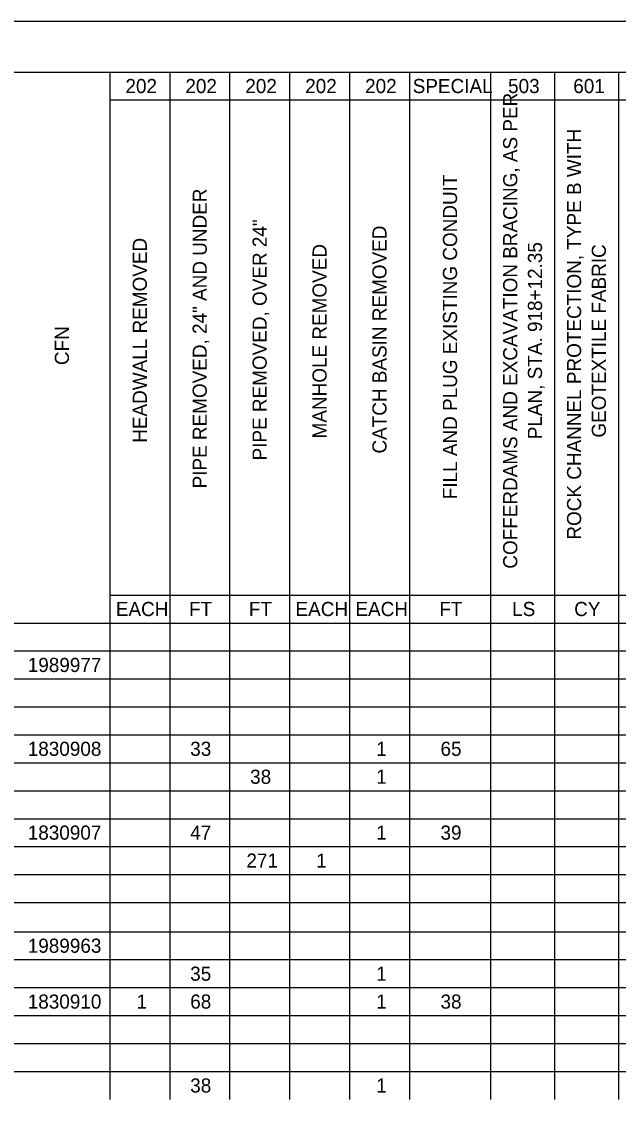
# Model space of a CAD drawing. Extents: x 0.2 to 34.2, y 0 to 22.
# Drawn here: x 9 to 14.91, y 11.35 to 22.03 of the extents above; entities that cross this region are included whole.
import ezdxf

# ---------------------------------------------------------------- set-up
doc = ezdxf.new("R2010")
doc.units = 0
for name, color, linetype in [('SH_Border', 7, 'Continuous'), ('SH_Cut_Line', 7, 'Continuous'), ('SH_Text', 7, 'Continuous')]:
    doc.layers.add(name, color=color, linetype=linetype)

msp = doc.modelspace()

# ---------------------------------------------------------------- linework, layer by layer
at = {"layer": 'SH_Border'}
msp.add_lwpolyline([(1.692, 21.525), (33.692, 21.525), (33.692, 0.525), (1.692, 0.525)], close=True, dxfattribs=at)
at = {"layer": 'SH_Cut_Line'}
msp.add_lwpolyline([(0.192, 0.025), (34.192, 0.025), (34.192, 22.025), (0.192, 22.025)], close=True, dxfattribs=at)
at = {"layer": 'SH_Text'}
for p, q in [((8.254, 21.525), (13.643, 21.525)), ((9.875, 21.525), (9.875, 21.249)), ((10.468, 21.525), (10.468, 21.249)), ((11.06, 21.525), (11.06, 21.249)), ((11.653, 21.525), (11.653, 21.249)), ((12.246, 21.525), (12.246, 21.249)), ((12.839, 21.525), (12.839, 21.249)), ((13.643, 21.525), (14.276, 21.525)), ((13.643, 21.525), (13.643, 21.249)), ((14.276, 21.525), (14.908, 21.525)), ((14.276, 21.525), (14.276, 21.249)), ((14.908, 21.525), (15.54, 21.525)), ((14.908, 21.525), (14.908, 21.249)), ((9.875, 21.249), (13.643, 21.249)), ((9.875, 21.249), (9.875, 20.972)), ((10.468, 21.249), (10.468, 20.972)), ((11.06, 21.249), (11.06, 20.972)), ((11.653, 21.249), (11.653, 20.972)), ((12.246, 21.249), (12.246, 20.972)), ((12.839, 21.249), (12.839, 20.972)), ((13.643, 21.249), (14.276, 21.249)), ((13.643, 21.249), (13.643, 20.972)), ((14.276, 21.249), (14.908, 21.249)), ((14.276, 21.249), (14.276, 20.972)), ((14.908, 21.249), (15.54, 21.249)), ((14.908, 21.249), (14.908, 20.972)), ((9.875, 20.972), (9.875, 20.695)), ((10.468, 20.972), (10.468, 20.695)), ((11.06, 20.972), (11.06, 20.695)), ((11.653, 20.972), (11.653, 20.695)), ((12.246, 20.972), (12.246, 20.695)), ((12.839, 20.972), (12.839, 20.695)), ((13.643, 20.972), (13.643, 20.695)), ((14.276, 20.972), (14.276, 20.695)), ((14.908, 20.972), (14.908, 20.695)), ((9.875, 20.695), (9.875, 20.418)), ((10.468, 20.695), (10.468, 20.418)), ((11.06, 20.695), (11.06, 20.418)), ((11.653, 20.695), (11.653, 20.418)), ((12.246, 20.695), (12.246, 20.418)), ((12.839, 20.695), (12.839, 20.418)), ((13.643, 20.695), (13.643, 20.418)), ((14.276, 20.695), (14.276, 20.418)), ((14.908, 20.695), (14.908, 20.418)), ((9.875, 20.418), (9.875, 20.142)), ((10.468, 20.418), (10.468, 20.142)), ((11.06, 20.418), (11.06, 20.142)), ((11.653, 20.418), (11.653, 20.142)), ((12.246, 20.418), (12.246, 20.142)), ((12.839, 20.418), (12.839, 20.142)), ((13.643, 20.418), (13.643, 20.142)), ((14.276, 20.418), (14.276, 20.142)), ((14.908, 20.418), (14.908, 20.142)), ((9.875, 20.142), (9.875, 19.865)), ((10.468, 20.142), (10.468, 19.865)), ((11.06, 20.142), (11.06, 19.865)), ((11.653, 20.142), (11.653, 19.865)), ((12.246, 20.142), (12.246, 19.865)), ((12.839, 20.142), (12.839, 19.865)), ((13.643, 20.142), (13.643, 19.865)), ((14.276, 20.142), (14.276, 19.865)), ((14.908, 20.142), (14.908, 19.865)), ((9.875, 19.865), (9.875, 19.588)), ((10.468, 19.865), (10.468, 19.588)), ((11.06, 19.865), (11.06, 19.588)), ((11.653, 19.865), (11.653, 19.588)), ((12.246, 19.865), (12.246, 19.588)), ((12.839, 19.865), (12.839, 19.588)), ((13.643, 19.865), (13.643, 19.588)), ((14.276, 19.865), (14.276, 19.588)), ((14.908, 19.865), (14.908, 19.588)), ((9.875, 19.588), (9.875, 19.312)), ((10.468, 19.588), (10.468, 19.312)), ((11.06, 19.588), (11.06, 19.312)), ((11.653, 19.588), (11.653, 19.312)), ((12.246, 19.588), (12.246, 19.312)), ((12.839, 19.588), (12.839, 19.312)), ((13.643, 19.588), (13.643, 19.312)), ((14.276, 19.588), (14.276, 19.312)), ((14.908, 19.588), (14.908, 19.312)), ((9.875, 19.312), (9.875, 19.035)), ((10.468, 19.312), (10.468, 19.035)), ((11.06, 19.312), (11.06, 19.035)), ((11.653, 19.312), (11.653, 19.035)), ((12.246, 19.312), (12.246, 19.035)), ((12.839, 19.312), (12.839, 19.035)), ((13.643, 19.312), (13.643, 19.035)), ((14.276, 19.312), (14.276, 19.035)), ((14.908, 19.312), (14.908, 19.035)), ((9.875, 19.035), (9.875, 18.758)), ((10.468, 19.035), (10.468, 18.758)), ((11.06, 19.035), (11.06, 18.758)), ((11.653, 19.035), (11.653, 18.758)), ((12.246, 19.035), (12.246, 18.758)), ((12.839, 19.035), (12.839, 18.758)), ((13.643, 19.035), (13.643, 18.758)), ((14.276, 19.035), (14.276, 18.758)), ((14.908, 19.035), (14.908, 18.758)), ((9.875, 18.758), (9.875, 18.482)), ((10.468, 18.758), (10.468, 18.482)), ((11.06, 18.758), (11.06, 18.482)), ((11.653, 18.758), (11.653, 18.482)), ((12.246, 18.758), (12.246, 18.482)), ((12.839, 18.758), (12.839, 18.482)), ((13.643, 18.758), (13.643, 18.482)), ((14.276, 18.758), (14.276, 18.482)), ((14.908, 18.758), (14.908, 18.482)), ((9.875, 18.482), (9.875, 18.205)), ((10.468, 18.482), (10.468, 18.205)), ((11.06, 18.482), (11.06, 18.205)), ((11.653, 18.482), (11.653, 18.205)), ((12.246, 18.482), (12.246, 18.205)), ((12.839, 18.482), (12.839, 18.205)), ((13.643, 18.482), (13.643, 18.205)), ((14.276, 18.482), (14.276, 18.205)), ((14.908, 18.482), (14.908, 18.205)), ((9.875, 18.205), (9.875, 16.347)), ((10.468, 18.205), (10.468, 16.347)), ((11.06, 18.205), (11.06, 16.347)), ((11.653, 18.205), (11.653, 16.347)), ((12.246, 18.205), (12.246, 16.347)), ((12.839, 18.205), (12.839, 16.347)), ((13.643, 18.205), (13.643, 16.347)), ((14.276, 18.205), (14.276, 16.347)), ((14.908, 18.205), (14.908, 16.347)), ((9.875, 16.347), (13.643, 16.347)), ((9.875, 16.347), (9.875, 16.07)), ((10.468, 16.347), (10.468, 16.07)), ((11.06, 16.347), (11.06, 16.07)), ((11.653, 16.347), (11.653, 16.07)), ((12.246, 16.347), (12.246, 16.07)), ((12.839, 16.347), (12.839, 16.07)), ((13.643, 16.347), (14.276, 16.347)), ((13.643, 16.347), (13.643, 16.07)), ((14.276, 16.347), (14.908, 16.347)), ((14.276, 16.347), (14.276, 16.07)), ((14.908, 16.347), (15.54, 16.347)), ((14.908, 16.347), (14.908, 16.07)), ((8.254, 16.07), (13.643, 16.07)), ((9.875, 16.07), (9.875, 15.794)), ((10.468, 16.07), (10.468, 15.794)), ((11.06, 16.07), (11.06, 15.794)), ((11.653, 16.07), (11.653, 15.794)), ((12.246, 16.07), (12.246, 15.794)), ((12.839, 16.07), (12.839, 15.794)), ((13.643, 16.07), (14.276, 16.07)), ((13.643, 16.07), (13.643, 15.794)), ((14.276, 16.07), (14.908, 16.07)), ((14.276, 16.07), (14.276, 15.794)), ((14.908, 16.07), (15.54, 16.07)), ((14.908, 16.07), (14.908, 15.794)), ((8.254, 15.794), (13.643, 15.794)), ((9.875, 15.794), (9.875, 15.517)), ((10.468, 15.794), (10.468, 15.517)), ((11.06, 15.794), (11.06, 15.517)), ((11.653, 15.794), (11.653, 15.517)), ((12.246, 15.794), (12.246, 15.517)), ((12.839, 15.794), (12.839, 15.517)), ((13.643, 15.794), (14.276, 15.794)), ((13.643, 15.794), (13.643, 15.517)), ((14.276, 15.794), (14.908, 15.794)), ((14.276, 15.794), (14.276, 15.517)), ((14.908, 15.794), (15.54, 15.794)), ((14.908, 15.794), (14.908, 15.517)), ((8.254, 15.517), (13.643, 15.517)), ((9.875, 15.517), (9.875, 15.24)), ((10.468, 15.517), (10.468, 15.24)), ((11.06, 15.517), (11.06, 15.24)), ((11.653, 15.517), (11.653, 15.24)), ((12.246, 15.517), (12.246, 15.24)), ((12.839, 15.517), (12.839, 15.24)), ((13.643, 15.517), (14.276, 15.517)), ((13.643, 15.517), (13.643, 15.24)), ((14.276, 15.517), (14.908, 15.517)), ((14.276, 15.517), (14.276, 15.24)), ((14.908, 15.517), (15.54, 15.517)), ((14.908, 15.517), (14.908, 15.24)), ((8.254, 15.24), (13.643, 15.24)), ((9.875, 15.24), (9.875, 14.963)), ((10.468, 15.24), (10.468, 14.963)), ((11.06, 15.24), (11.06, 14.963)), ((11.653, 15.24), (11.653, 14.963)), ((12.246, 15.24), (12.246, 14.963)), ((12.839, 15.24), (12.839, 14.963)), ((13.643, 15.24), (14.276, 15.24)), ((13.643, 15.24), (13.643, 14.963)), ((14.276, 15.24), (14.908, 15.24)), ((14.276, 15.24), (14.276, 14.963)), ((14.908, 15.24), (15.54, 15.24)), ((14.908, 15.24), (14.908, 14.963)), ((8.254, 14.963), (13.643, 14.963)), ((9.875, 14.963), (9.875, 14.687)), ((10.468, 14.963), (10.468, 14.687)), ((11.06, 14.963), (11.06, 14.687)), ((11.653, 14.963), (11.653, 14.687)), ((12.246, 14.963), (12.246, 14.687)), ((12.839, 14.963), (12.839, 14.687)), ((13.643, 14.963), (14.276, 14.963)), ((13.643, 14.963), (13.643, 14.687)), ((14.276, 14.963), (14.908, 14.963)), ((14.276, 14.963), (14.276, 14.687)), ((14.908, 14.963), (15.54, 14.963)), ((14.908, 14.963), (14.908, 14.687)), ((8.254, 14.687), (13.643, 14.687)), ((9.875, 14.687), (9.875, 14.41)), ((10.468, 14.687), (10.468, 14.41)), ((11.06, 14.687), (11.06, 14.41)), ((11.653, 14.687), (11.653, 14.41)), ((12.246, 14.687), (12.246, 14.41)), ((12.839, 14.687), (12.839, 14.41)), ((13.643, 14.687), (14.276, 14.687)), ((13.643, 14.687), (13.643, 14.41)), ((14.276, 14.687), (14.908, 14.687)), ((14.276, 14.687), (14.276, 14.41)), ((14.908, 14.687), (15.54, 14.687)), ((14.908, 14.687), (14.908, 14.41)), ((8.254, 14.41), (13.643, 14.41)), ((9.875, 14.41), (9.875, 14.133)), ((10.468, 14.41), (10.468, 14.133)), ((11.06, 14.41), (11.06, 14.133)), ((11.653, 14.41), (11.653, 14.133)), ((12.246, 14.41), (12.246, 14.133)), ((12.839, 14.41), (12.839, 14.133)), ((13.643, 14.41), (14.276, 14.41)), ((13.643, 14.41), (13.643, 14.133)), ((14.276, 14.41), (14.908, 14.41)), ((14.276, 14.41), (14.276, 14.133)), ((14.908, 14.41), (15.54, 14.41)), ((14.908, 14.41), (14.908, 14.133)), ((8.254, 14.133), (13.643, 14.133)), ((9.875, 14.133), (9.875, 13.857)), ((10.468, 14.133), (10.468, 13.857)), ((11.06, 14.133), (11.06, 13.857)), ((11.653, 14.133), (11.653, 13.857)), ((12.246, 14.133), (12.246, 13.857)), ((12.839, 14.133), (12.839, 13.857)), ((13.643, 14.133), (14.276, 14.133)), ((13.643, 14.133), (13.643, 13.857)), ((14.276, 14.133), (14.908, 14.133)), ((14.276, 14.133), (14.276, 13.857)), ((14.908, 14.133), (15.54, 14.133)), ((14.908, 14.133), (14.908, 13.857)), ((8.254, 13.857), (13.643, 13.857)), ((9.875, 13.857), (9.875, 13.58)), ((10.468, 13.857), (10.468, 13.58)), ((11.06, 13.857), (11.06, 13.58)), ((11.653, 13.857), (11.653, 13.58)), ((12.246, 13.857), (12.246, 13.58)), ((12.839, 13.857), (12.839, 13.58)), ((13.643, 13.857), (14.276, 13.857)), ((13.643, 13.857), (13.643, 13.58)), ((14.276, 13.857), (14.908, 13.857)), ((14.276, 13.857), (14.276, 13.58)), ((14.908, 13.857), (15.54, 13.857)), ((14.908, 13.857), (14.908, 13.58)), ((8.254, 13.58), (13.643, 13.58)), ((9.875, 13.58), (9.875, 13.303)), ((10.468, 13.58), (10.468, 13.303)), ((11.06, 13.58), (11.06, 13.303)), ((11.653, 13.58), (11.653, 13.303)), ((12.246, 13.58), (12.246, 13.303)), ((12.839, 13.58), (12.839, 13.303)), ((13.643, 13.58), (14.276, 13.58)), ((13.643, 13.58), (13.643, 13.303)), ((14.276, 13.58), (14.908, 13.58)), ((14.276, 13.58), (14.276, 13.303)), ((14.908, 13.58), (15.54, 13.58)), ((14.908, 13.58), (14.908, 13.303)), ((8.254, 13.303), (13.643, 13.303)), ((9.875, 13.303), (9.875, 13.013)), ((10.468, 13.303), (10.468, 13.013)), ((11.06, 13.303), (11.06, 13.013)), ((11.653, 13.303), (11.653, 13.013)), ((12.246, 13.303), (12.246, 13.013)), ((12.839, 13.303), (12.839, 13.013)), ((13.643, 13.303), (14.276, 13.303)), ((13.643, 13.303), (13.643, 13.013)), ((14.276, 13.303), (14.908, 13.303)), ((14.276, 13.303), (14.276, 13.013)), ((14.908, 13.303), (15.54, 13.303)), ((14.908, 13.303), (14.908, 13.013)), ((8.254, 13.013), (13.643, 13.013)), ((9.875, 13.013), (9.875, 12.737)), ((10.468, 13.013), (10.468, 12.737)), ((11.06, 13.013), (11.06, 12.737)), ((11.653, 13.013), (11.653, 12.737)), ((12.246, 13.013), (12.246, 12.737)), ((12.839, 13.013), (12.839, 12.737)), ((13.643, 13.013), (14.276, 13.013)), ((13.643, 13.013), (13.643, 12.737)), ((14.276, 13.013), (14.908, 13.013)), ((14.276, 13.013), (14.276, 12.737)), ((14.908, 13.013), (15.54, 13.013)), ((14.908, 13.013), (14.908, 12.737)), ((8.254, 12.737), (13.643, 12.737)), ((9.875, 12.737), (9.875, 12.46)), ((10.468, 12.737), (10.468, 12.46)), ((11.06, 12.737), (11.06, 12.46)), ((11.653, 12.737), (11.653, 12.46)), ((12.246, 12.737), (12.246, 12.46)), ((12.839, 12.737), (12.839, 12.46)), ((13.643, 12.737), (14.276, 12.737)), ((13.643, 12.737), (13.643, 12.46)), ((14.276, 12.737), (14.908, 12.737)), ((14.276, 12.737), (14.276, 12.46)), ((14.908, 12.737), (15.54, 12.737)), ((14.908, 12.737), (14.908, 12.46)), ((8.254, 12.46), (13.643, 12.46)), ((9.875, 12.46), (9.875, 12.183)), ((10.468, 12.46), (10.468, 12.183)), ((11.06, 12.46), (11.06, 12.183)), ((11.653, 12.46), (11.653, 12.183)), ((12.246, 12.46), (12.246, 12.183)), ((12.839, 12.46), (12.839, 12.183)), ((13.643, 12.46), (14.276, 12.46)), ((13.643, 12.46), (13.643, 12.183)), ((14.276, 12.46), (14.908, 12.46)), ((14.276, 12.46), (14.276, 12.183)), ((14.908, 12.46), (15.54, 12.46)), ((14.908, 12.46), (14.908, 12.183)), ((8.254, 12.183), (13.643, 12.183)), ((9.875, 12.183), (9.875, 11.906)), ((10.468, 12.183), (10.468, 11.906)), ((11.06, 12.183), (11.06, 11.906)), ((11.653, 12.183), (11.653, 11.906)), ((12.246, 12.183), (12.246, 11.906)), ((12.839, 12.183), (12.839, 11.906)), ((13.643, 12.183), (14.276, 12.183)), ((13.643, 12.183), (13.643, 11.906)), ((14.276, 12.183), (14.908, 12.183)), ((14.276, 12.183), (14.276, 11.906)), ((14.908, 12.183), (15.54, 12.183)), ((14.908, 12.183), (14.908, 11.906)), ((8.254, 11.906), (13.643, 11.906)), ((9.875, 11.906), (9.875, 11.63)), ((10.468, 11.906), (10.468, 11.63)), ((11.06, 11.906), (11.06, 11.63)), ((11.653, 11.906), (11.653, 11.63)), ((12.246, 11.906), (12.246, 11.63)), ((12.839, 11.906), (12.839, 11.63)), ((13.643, 11.906), (14.276, 11.906)), ((13.643, 11.906), (13.643, 11.63)), ((14.276, 11.906), (14.908, 11.906)), ((14.276, 11.906), (14.276, 11.63)), ((14.908, 11.906), (15.54, 11.906)), ((14.908, 11.906), (14.908, 11.63)), ((8.254, 11.63), (13.643, 11.63)), ((9.875, 11.63), (9.875, 11.353)), ((10.468, 11.63), (10.468, 11.353)), ((11.06, 11.63), (11.06, 11.353)), ((11.653, 11.63), (11.653, 11.353)), ((12.246, 11.63), (12.246, 11.353)), ((12.839, 11.63), (12.839, 11.353)), ((13.643, 11.63), (14.276, 11.63)), ((13.643, 11.63), (13.643, 11.353)), ((14.276, 11.63), (14.908, 11.63)), ((14.276, 11.63), (14.276, 11.353)), ((14.908, 11.63), (15.54, 11.63)), ((14.908, 11.63), (14.908, 11.353))]:
    msp.add_line(p, q, dxfattribs=at)

# ---------------------------------------------------------------- texts
for s, p in [('202', (10.029, 21.317)), ('202', (10.622, 21.317)), ('202', (11.215, 21.317)), ('202', (11.808, 21.317)), ('202', (12.401, 21.317)), ('SPECIAL', (12.872, 21.317)), ('503', (13.816, 21.317)), ('601', (14.461, 21.317)), ('EACH', (9.934, 16.139)), ('FT', (10.658, 16.139)), ('FT', (11.251, 16.139)), ('EACH', (11.712, 16.139)), ('EACH', (12.305, 16.139)), ('FT', (13.135, 16.139)), ('LS', (13.856, 16.139)), ('CY', (14.47, 16.139)), ('1989977', (9.062, 15.585)), ('1830908', (9.062, 14.755)), ('33', (10.67, 14.755)), ('1', (12.51, 14.755)), ('65', (13.147, 14.755)), ('38', (11.263, 14.478)), ('1', (12.51, 14.478)), ('1830907', (9.062, 13.925)), ('47', (10.67, 13.925)), ('1', (12.51, 13.925)), ('39', (13.147, 13.925)), ('271', (11.226, 13.648)), ('1', (11.917, 13.648)), ('1989963', (9.062, 12.805)), ('35', (10.67, 12.528)), ('1', (12.51, 12.528)), ('1830910', (9.062, 12.252)), ('1', (10.138, 12.252)), ('68', (10.67, 12.252)), ('1', (12.51, 12.252)), ('38', (13.147, 12.252)), ('38', (10.67, 11.421)), ('1', (12.51, 11.421))]:
    msp.add_text(s, height=0.14, dxfattribs=at).set_placement(p)
for s, p in [('COFFERDAMS AND EXCAVATION BRACING, AS PER ', (13.907, 16.608)), ('ROCK CHANNEL PROTECTION, TYPE B WITH ', (14.539, 16.896)), ('FILL AND PLUG EXISTING CONDUIT', (13.311, 17.296)), ('PIPE REMOVED, 24" AND UNDER', (10.834, 17.403)), ('PIPE REMOVED, OVER 24"', (11.427, 17.68)), ('CATCH BASIN REMOVED', (12.613, 17.748)), ('HEADWALL REMOVED', (10.241, 17.855)), ('MANHOLE REMOVED', (12.02, 17.898)), ('PLAN, STA. 918+12.35', (14.152, 17.89)), ('GEOTEXTILE FABRIC', (14.784, 17.906)), ('CFN', (9.47, 18.624))]:
    msp.add_text(s, height=0.14, rotation=90, dxfattribs=at).set_placement(p)

doc.saveas('drawing.dxf')
